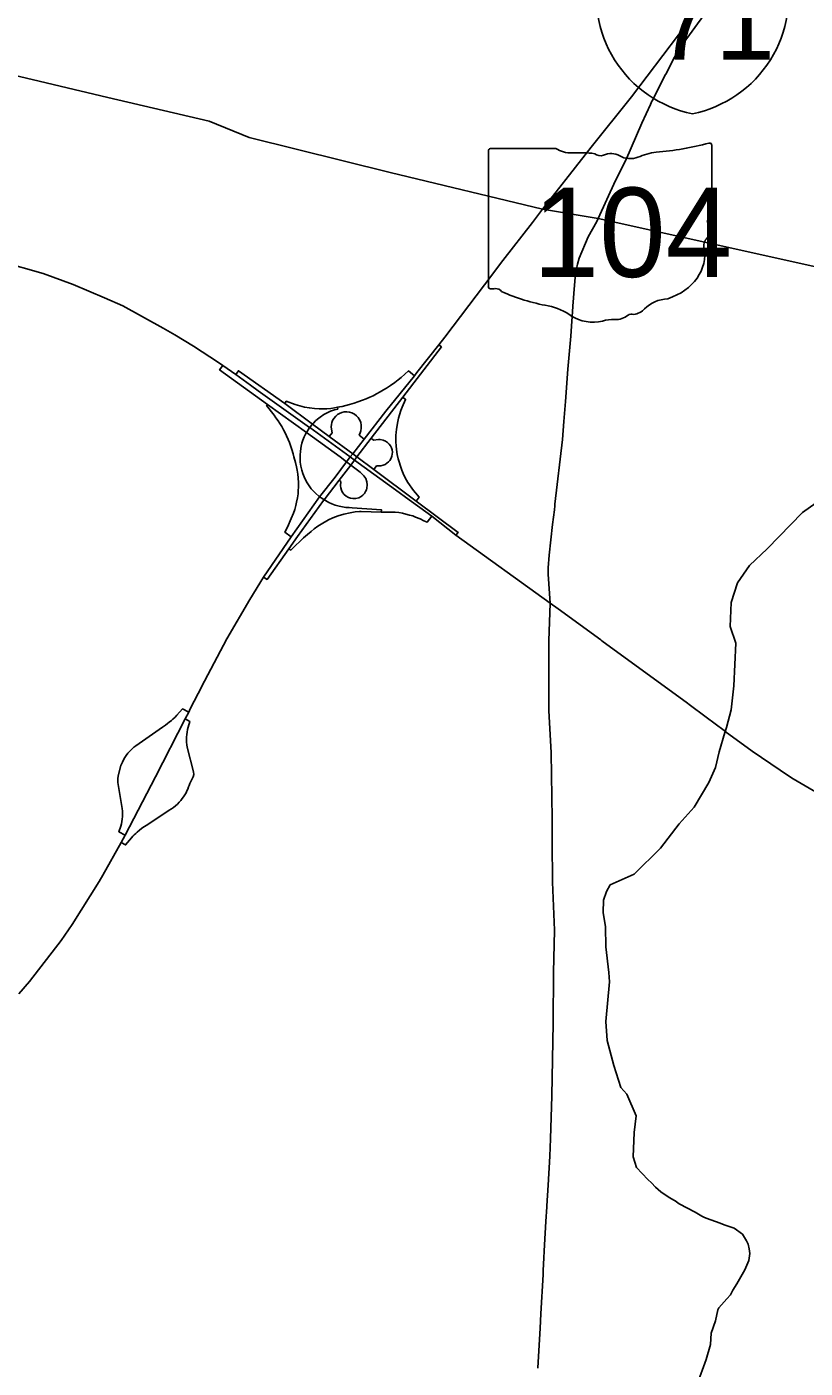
# Model space of a CAD drawing. Extents: x -1146 to -445, y -1283 to -822.
# Drawn here: x -924.4 to -894.1, y -1156.9 to -1104.6 of the extents above; entities that cross this region are included whole.
import ezdxf

# ---------------------------------------------------------------- set-up
doc = ezdxf.new("R2010")
doc.units = 0
for name, color, linetype in [('GM_X_Interchange_Ramps', 7, 'Continuous'), ('GM_X_Interstate_Route', 7, 'Continuous'), ('GM_X_Interstate_Shield', 7, 'Continuous'), ('GM_X_State_Route', 7, 'Continuous'), ('GM_X_State_Shield', 7, 'Continuous'), ('GM_X_Township', 7, 'Continuous')]:
    doc.layers.add(name, color=color, linetype=linetype)

msp = doc.modelspace()

# ---------------------------------------------------------------- linework, layer by layer
at = {"layer": 'GM_X_Interchange_Ramps'}
for points in [[(-915.223, -1126.03), (-915.087, -1126.118), (-914.237, -1124.918), (-913.9, -1124.442), (-912.889, -1123.039), (-912.867, -1123.01), (-912.283, -1122.25), (-911.827, -1121.656), (-911.679, -1121.463), (-911.587, -1121.343), (-911.029, -1120.616), (-909.799, -1119.013), (-908.294, -1117.052), (-908.395, -1116.973)], [(-916.813, -1117.78), (-916.933, -1117.944), (-915.07, -1119.293), (-913.55, -1120.395), (-912.242, -1121.342), (-911.987, -1121.535), (-911.827, -1121.656), (-911.457, -1121.935), (-911.315, -1122.072), (-911.244, -1122.188), (-911.197, -1122.31), (-911.183, -1122.431), (-911.197, -1122.556), (-911.217, -1122.622), (-911.245, -1122.687), (-911.294, -1122.763), (-911.353, -1122.828), (-911.415, -1122.877), (-911.517, -1122.93), (-911.633, -1122.96), (-911.743, -1122.963), (-911.84, -1122.947), (-911.912, -1122.922), (-912.003, -1122.87), (-912.079, -1122.804), (-912.144, -1122.721), (-912.189, -1122.63), (-912.211, -1122.551), (-912.222, -1122.468), (-912.212, -1122.305), (-912.283, -1122.25)], [(-907.727, -1124.391), (-907.645, -1124.281), (-909.28, -1123.069), (-910.923, -1121.836), (-911.587, -1121.343), (-911.749, -1121.223), (-912.661, -1120.546), (-913.313, -1120.062), (-914.399, -1119.255), (-916.199, -1117.98), (-916.308, -1118.13)], [(-909.344, -1118.176), (-909.581, -1117.991), (-909.866, -1118.241), (-909.979, -1118.334), (-910.111, -1118.436), (-910.282, -1118.558), (-910.435, -1118.66), (-910.55, -1118.731), (-910.681, -1118.808), (-910.818, -1118.883), (-910.959, -1118.955), (-911.087, -1119.016), (-911.22, -1119.074), (-911.368, -1119.135), (-911.545, -1119.2), (-911.687, -1119.248), (-911.869, -1119.302), (-912.018, -1119.342), (-912.164, -1119.372), (-912.263, -1119.392), (-912.348, -1119.403), (-912.454, -1119.426), (-912.599, -1119.449), (-912.757, -1119.461), (-912.901, -1119.466), (-913.053, -1119.464), (-913.242, -1119.453), (-913.438, -1119.43), (-913.625, -1119.396), (-913.812, -1119.352), (-913.985, -1119.301), (-914.339, -1119.174), (-914.399, -1119.255)], [(-915.07, -1119.293), (-915.106, -1119.341), (-914.81, -1119.715), (-914.739, -1119.812), (-914.651, -1119.938), (-914.589, -1120.034), (-914.514, -1120.158), (-914.443, -1120.285), (-914.371, -1120.423), (-914.326, -1120.518), (-914.261, -1120.663), (-914.213, -1120.782), (-914.171, -1120.897), (-914.121, -1121.047), (-914.071, -1121.217), (-914.04, -1121.34), (-913.978, -1121.555), (-913.936, -1121.726), (-913.911, -1121.851), (-913.887, -1122.007), (-913.871, -1122.156), (-913.861, -1122.351), (-913.862, -1122.51), (-913.869, -1122.659), (-913.88, -1122.777), (-913.903, -1122.94), (-913.933, -1123.1), (-913.964, -1123.233), (-914.008, -1123.386), (-914.056, -1123.528), (-914.141, -1123.736), (-914.285, -1124.078), (-914.392, -1124.275), (-914.14, -1124.455)], [(-909.28, -1123.069), (-909.161, -1122.909), (-909.305, -1122.744), (-909.385, -1122.646), (-909.449, -1122.56), (-909.537, -1122.433), (-909.597, -1122.336), (-909.653, -1122.241), (-909.726, -1122.103), (-909.778, -1121.993), (-909.836, -1121.859), (-909.894, -1121.7), (-909.946, -1121.536), (-909.978, -1121.414), (-910.013, -1121.249), (-910.044, -1121.053), (-910.059, -1120.905), (-910.068, -1120.748), (-910.069, -1120.611), (-910.066, -1120.5), (-910.057, -1120.372), (-910.047, -1120.27), (-910.024, -1120.107), (-909.996, -1119.959), (-909.965, -1119.829), (-909.927, -1119.695), (-909.872, -1119.531), (-909.82, -1119.399), (-909.688, -1119.1), (-909.799, -1119.013)], [(-912.348, -1119.403), (-912.335, -1119.479), (-912.453, -1119.511), (-912.614, -1119.56), (-912.748, -1119.622), (-912.874, -1119.693), (-913.015, -1119.788), (-913.121, -1119.873), (-913.194, -1119.939), (-913.279, -1120.025), (-913.313, -1120.062), (-913.351, -1120.106), (-913.423, -1120.199), (-913.44, -1120.222), (-913.521, -1120.345), (-913.55, -1120.395), (-913.584, -1120.457), (-913.636, -1120.564), (-913.688, -1120.694), (-913.725, -1120.81), (-913.755, -1120.924), (-913.788, -1121.118), (-913.801, -1121.277), (-913.802, -1121.409), (-913.793, -1121.544), (-913.772, -1121.695), (-913.737, -1121.854), (-913.695, -1121.99), (-913.646, -1122.116), (-913.592, -1122.232), (-913.527, -1122.35), (-913.451, -1122.468), (-913.364, -1122.583), (-913.279, -1122.679), (-913.187, -1122.77), (-913.064, -1122.875), (-913.041, -1122.892), (-912.958, -1122.953), (-912.867, -1123.01), (-912.814, -1123.044), (-912.679, -1123.115), (-912.558, -1123.168), (-912.43, -1123.215), (-912.279, -1123.259), (-912.141, -1123.288), (-912.02, -1123.306), (-911.888, -1123.318), (-911.774, -1123.324), (-910.634, -1123.401), (-910.635, -1123.494)], [(-912.661, -1120.546), (-912.549, -1120.396), (-912.579, -1120.254), (-912.585, -1120.169), (-912.578, -1120.08), (-912.559, -1119.997), (-912.531, -1119.924), (-912.483, -1119.839), (-912.411, -1119.752), (-912.34, -1119.693), (-912.258, -1119.644), (-912.177, -1119.611), (-912.081, -1119.589), (-911.978, -1119.583), (-911.88, -1119.595), (-911.78, -1119.625), (-911.684, -1119.674), (-911.606, -1119.733), (-911.543, -1119.799), (-911.495, -1119.867), (-911.462, -1119.934), (-911.438, -1120.002), (-911.418, -1120.106), (-911.416, -1120.217), (-911.431, -1120.32), (-911.453, -1120.397), (-911.495, -1120.491), (-911.298, -1120.644)], [(-911.029, -1120.616), (-910.934, -1120.691), (-910.751, -1120.666), (-910.677, -1120.666), (-910.566, -1120.686), (-910.473, -1120.724), (-910.395, -1120.777), (-910.331, -1120.839), (-910.28, -1120.909), (-910.244, -1120.981), (-910.218, -1121.065), (-910.206, -1121.15), (-910.209, -1121.234), (-910.226, -1121.317), (-910.255, -1121.395), (-910.303, -1121.476), (-910.351, -1121.532), (-910.418, -1121.59), (-910.485, -1121.631), (-910.561, -1121.663), (-910.652, -1121.684), (-910.819, -1121.692), (-910.923, -1121.836)], [(-914.237, -1124.918), (-914.155, -1124.972), (-913.982, -1124.797), (-913.814, -1124.635), (-913.662, -1124.495), (-913.51, -1124.36), (-913.372, -1124.243), (-913.256, -1124.148), (-913.113, -1124.041), (-912.983, -1123.956), (-912.695, -1123.798), (-912.524, -1123.721), (-912.318, -1123.642), (-912.096, -1123.574), (-911.847, -1123.517), (-911.653, -1123.487), (-911.488, -1123.47), (-911.422, -1123.466), (-910.635, -1123.494), (-910.39, -1123.489), (-910.248, -1123.489), (-910.102, -1123.495), (-909.958, -1123.512), (-909.809, -1123.538), (-909.679, -1123.566), (-909.532, -1123.605), (-909.414, -1123.642), (-909.299, -1123.683), (-909.123, -1123.755), (-908.978, -1123.826), (-908.851, -1123.887), (-908.672, -1123.646)], [(-918.138, -1131.287), (-918.375, -1131.162), (-918.599, -1131.41), (-918.668, -1131.481), (-918.751, -1131.56), (-918.812, -1131.614), (-918.894, -1131.683), (-918.958, -1131.732), (-919.042, -1131.793), (-919.161, -1131.873), (-920.196, -1132.596), (-920.269, -1132.653), (-920.343, -1132.719), (-920.422, -1132.797), (-920.502, -1132.889), (-920.567, -1132.974), (-920.62, -1133.054), (-920.675, -1133.147), (-920.721, -1133.238), (-920.785, -1133.362), (-920.88, -1133.771), (-920.893, -1133.882)], [(-917.943, -1133.715), (-917.945, -1133.615), (-918.198, -1132.651), (-918.21, -1132.556), (-918.217, -1132.457), (-918.219, -1132.366), (-918.217, -1132.266), (-918.209, -1132.165), (-918.196, -1132.066), (-918.178, -1131.971), (-918.154, -1131.87), (-918.09, -1131.654), (-918.278, -1131.555)], [(-920.893, -1133.882), (-920.897, -1134.025), (-920.737, -1134.96), (-920.725, -1135.05), (-920.717, -1135.152), (-920.714, -1135.254), (-920.718, -1135.352), (-920.728, -1135.459), (-920.742, -1135.552), (-920.759, -1135.635), (-920.786, -1135.738), (-920.855, -1135.949), (-920.613, -1136.077)], [(-920.774, -1136.366), (-920.593, -1136.462), (-920.361, -1136.184), (-920.309, -1136.126), (-920.257, -1136.072), (-920.198, -1136.014), (-920.141, -1135.962), (-920.05, -1135.886), (-919.974, -1135.827), (-919.883, -1135.764), (-919.774, -1135.695), (-918.895, -1135.114), (-918.804, -1135.057), (-918.726, -1135.001), (-918.647, -1134.938), (-918.579, -1134.876), (-918.504, -1134.8), (-918.449, -1134.737), (-918.388, -1134.66), (-918.335, -1134.586), (-918.286, -1134.507), (-918.242, -1134.43), (-918.205, -1134.354), (-918.174, -1134.284), (-918.14, -1134.201), (-918.117, -1134.141), (-918.097, -1134.073), (-917.968, -1133.807), (-917.943, -1133.715)]]:
    msp.add_lwpolyline(points, dxfattribs=at)
at = {"layer": 'GM_X_Interstate_Route'}
for points in [[(-902.461, -1109.267), (-900.891, -1107.3), (-899.054, -1104.889), (-897.704, -1103.196), (-896.327, -1101.431), (-896.05, -1101.076), (-895.664, -1100.526), (-895.305, -1099.975), (-894.933, -1099.322), (-894.547, -1098.59)], [(-904.347, -1111.675), (-902.701, -1109.567), (-902.461, -1109.267)], [(-918.68, -1116.588), (-919.128, -1116.32), (-920.698, -1115.452), (-921.421, -1115.142), (-922.643, -1114.621), (-923.8, -1114.196), (-925.452, -1113.725), (-928.801, -1112.823), (-929.653, -1112.604), (-931.972, -1112.008), (-933.318, -1111.662), (-934.577, -1111.334), (-935.141, -1111.186), (-936.719, -1110.793), (-937.723, -1110.53)], [(-906.618, -1114.634), (-905.899, -1113.688), (-904.751, -1112.204), (-904.358, -1111.689), (-904.347, -1111.675)], [(-908.163, -1116.668), (-906.618, -1114.634)], [(-916.813, -1117.78), (-916.98, -1117.663), (-917.951, -1117.023), (-918.68, -1116.588)], [(-908.395, -1116.973), (-908.165, -1116.671), (-908.163, -1116.668)], [(-909.249, -1118.056), (-908.395, -1116.973)], [(-916.308, -1118.13), (-916.813, -1117.78)], [(-911.842, -1121.343), (-913.423, -1120.199), (-913.432, -1120.192), (-915.426, -1118.767), (-915.725, -1118.55), (-916.308, -1118.13)], [(-911.842, -1121.343), (-911.749, -1121.223), (-911.298, -1120.644), (-910.456, -1119.561), (-909.344, -1118.176), (-909.249, -1118.056)], [(-914.14, -1124.455), (-913.048, -1122.902), (-913.041, -1122.892), (-912.438, -1122.133), (-911.987, -1121.535), (-911.842, -1121.343)], [(-909.943, -1122.728), (-911.679, -1121.463), (-911.842, -1121.343)], [(-903.741, -1127.268), (-904.06, -1127.035), (-907.727, -1124.391), (-908.672, -1123.646), (-909.696, -1122.909), (-909.943, -1122.728)], [(-915.223, -1126.03), (-914.14, -1124.455)], [(-917.763, -1130.558), (-917.516, -1130.079), (-916.65, -1128.428), (-915.762, -1126.895), (-915.223, -1126.03)], [(-902.043, -1128.506), (-902.086, -1128.474), (-903.741, -1127.268)], [(-898.65, -1130.986), (-898.708, -1130.943), (-902.043, -1128.506)], [(-918.076, -1131.165), (-917.763, -1130.558)], [(-919.433, -1133.812), (-919.433, -1133.812), (-918.278, -1131.555), (-918.138, -1131.287), (-918.076, -1131.165)], [(-897.282, -1132.007), (-897.976, -1131.483), (-898.65, -1130.986)], [(-894.588, -1133.882), (-894.737, -1133.793), (-896.186, -1132.807), (-897.237, -1132.041), (-897.282, -1132.007)], [(-921.487, -1137.641), (-920.774, -1136.366), (-920.613, -1136.077), (-919.433, -1133.812)], [(-889.908, -1136.261), (-890.993, -1135.789), (-892.156, -1135.231), (-892.864, -1134.871), (-893.811, -1134.345), (-894.588, -1133.882)], [(-924.752, -1142.273), (-924.336, -1141.79), (-923.11, -1140.191), (-922.672, -1139.564), (-921.629, -1137.894), (-921.487, -1137.641)]]:
    msp.add_lwpolyline(points, dxfattribs=at)
at = {"layer": 'GM_X_Interstate_Shield'}
for centre, start, end in [((-897.577, -1103.374), 165.8066, 258.463), ((-899.452, -1103.374), 281.537, 14.1934)]:
    msp.add_arc(centre, 4.688, start, end, dxfattribs=at)
at = {"layer": 'GM_X_State_Route'}
for points in [[(-899.551, -1106.418), (-899.222, -1105.756), (-898.978, -1105.371), (-897.97, -1103.984), (-896.862, -1102.61), (-896.57, -1102.284), (-896.244, -1101.94), (-895.928, -1101.644), (-895.333, -1101.143), (-895.269, -1101.093)], [(-900.094, -1107.477), (-900.089, -1107.466), (-899.563, -1106.44), (-899.551, -1106.418)], [(-902.184, -1112.047), (-902.183, -1112.045), (-901.514, -1110.571), (-901.112, -1109.775), (-900.489, -1108.339), (-900.148, -1107.599), (-900.094, -1107.477)], [(-903.171, -1115.471), (-903.11, -1114.644), (-903.066, -1114.198), (-903.035, -1114.008), (-902.993, -1113.832), (-902.926, -1113.592), (-902.579, -1112.763), (-902.242, -1112.166), (-902.184, -1112.047)], [(-903.875, -1123.181), (-903.581, -1120.661), (-903.53, -1119.964), (-903.459, -1119.178), (-903.368, -1117.92), (-903.257, -1116.628), (-903.171, -1115.474), (-903.171, -1115.471)], [(-904.109, -1129.836), (-904.108, -1128.543), (-904.108, -1128.507), (-904.06, -1127.035), (-904.141, -1125.915), (-904.139, -1125.664), (-904.095, -1125.173), (-903.964, -1123.976), (-903.895, -1123.405), (-903.883, -1123.25), (-903.879, -1123.211), (-903.875, -1123.181)], [(-903.98, -1136.267), (-903.986, -1136.138), (-903.975, -1135.44), (-904.024, -1132.87), (-904.111, -1131.224), (-904.11, -1129.921), (-904.11, -1129.893), (-904.109, -1129.836)], [(-904.05, -1147.912), (-903.991, -1146.243), (-903.94, -1143.409), (-903.929, -1141.432), (-903.886, -1139.786), (-903.967, -1137.909), (-903.977, -1136.325), (-903.98, -1136.267)], [(-904.316, -1152.805), (-904.279, -1152.055), (-904.228, -1151.141), (-904.193, -1150.564), (-904.191, -1150.527), (-904.142, -1149.721), (-904.074, -1148.593), (-904.05, -1147.912)], [(-904.535, -1156.857), (-904.534, -1156.844), (-904.448, -1155.293), (-904.418, -1154.745), (-904.335, -1153.202)], [(-904.335, -1153.202), (-904.328, -1153.051), (-904.316, -1152.805)]]:
    msp.add_lwpolyline(points, dxfattribs=at)
at = {"layer": 'GM_X_State_Shield'}
for p, q in [((-903.832, -1109.325), (-906.381, -1109.325)), ((-897.765, -1111.958), (-897.765, -1109.194)), ((-906.466, -1109.416), (-906.466, -1114.699)), ((-897.766, -1111.957), (-897.765, -1111.958))]:
    msp.add_line(p, q, dxfattribs=at)
for centre, major_axis, start_param, end_param in [((-906.366, -1109.405), (0.101, 0), 1.712693, 3.28349), ((-903.226, -1108.712), (0.978, 0), 4.042523, 4.731795), ((-900.865, -1102.123), (9.227, 0), 4.814394, 5.042369), ((-897.862, -1109.183), (0.0969, 0), 6.141152, 7.989035), ((-902.901, -1112.291), (3.51, 0), 1.404758, 1.657858), ((-902.105, -1109.378), (0.282, 0), 3.836095, 5.185415), ((-901.69, -1109.988), (0.586, 0), 0.950623, 2.079405), ((-900.934, -1109.151), (0.705, 0), 4.081561, 5.145723), ((-899.688, -1110.939), (1.856, 0), 1.699011, 2.107814), ((-897.869, -1111.969), (0.104, 0), 5.05454, 6.418171), ((-897.788, -1112.161), (0.15, 0), 1.883978, 3.671073), ((-898.741, -1112.51), (0.9, 0), 5.934695, 6.695948), ((-897.418, -1113.115), (0.655, 0), 2.387724, 3.262537), ((-900.348, -1113.466), (2.308, 0), 5.101752, 6.440018), ((-906.366, -1114.711), (0.102, 0), 3.00124, 4.508301), ((-906.35, -1114.17), (0.776, 0), 4.665946, 4.897461), ((-906.191, -1115.004), (0.28, 0), 0.519207, 1.627899), ((-902.658, -1110.257), (6.663, 0), 4.195997, 4.488961), ((-904.645, -1117.073), (2.085, 0), 0.823519, 1.323587), ((-900.976, -1115.211), (0.746, 0), 4.937069, 5.64225), ((-899.375, -1116.183), (1.264, 0), 1.647645, 2.488434), ((-902.39, -1115.03), (1.323, 0), 4.026481, 4.996735), ((-901.626, -1116.857), (1.087, 0), 1.495662, 1.94098), ((-901.529, -1115.426), (0.705, 0), 4.691044, 5.507374), ((-900.891, -1115.938), (0.198, 0), 1.147584, 2.315152)]:
    msp.add_ellipse(centre, major_axis=major_axis, ratio=0.8, start_param=start_param, end_param=end_param, dxfattribs=at)
at = {"layer": 'GM_X_Township'}
for points in [[(-891.411, -1104.525), (-891.013, -1105.536), (-890.797, -1106.62), (-890.038, -1109.149), (-889.279, -1111.425), (-888.954, -1111.93), (-888.159, -1112.508), (-887.617, -1112.653), (-885.522, -1112.833), (-885.269, -1113.05), (-884.908, -1113.917), (-884.872, -1114.387), (-885.052, -1115.145), (-885.182, -1115.826), (-902.183, -1112.045), (-904.358, -1111.689), (-910.289, -1110.249), (-915.786, -1108.893), (-917.339, -1108.257), (-921.29, -1107.327), (-927.148, -1105.948)], [(-898.329, -1157.484), (-897.985, -1156.523), (-897.812, -1155.932), (-897.785, -1155.488), (-897.621, -1155.015), (-897.526, -1154.578), (-897.485, -1154.507), (-897.177, -1154.153), (-897.035, -1154), (-896.939, -1153.814), (-896.793, -1153.569), (-896.478, -1153.021), (-896.326, -1152.659), (-896.28, -1152.391), (-896.312, -1152.207), (-896.344, -1152.024), (-896.414, -1151.89), (-896.571, -1151.639), (-896.898, -1151.406), (-897.284, -1151.27), (-897.431, -1151.202), (-897.982, -1151.005), (-898.067, -1150.975), (-898.148, -1150.93), (-898.416, -1150.783), (-899.029, -1150.448), (-899.193, -1150.339), (-899.24, -1150.308), (-899.401, -1150.219), (-899.578, -1150.096), (-899.752, -1149.989), (-899.962, -1149.798), (-900.116, -1149.627), (-900.257, -1149.5), (-900.697, -1149.032), (-900.826, -1148.615), (-900.781, -1147.677), (-900.706, -1147.019), (-901.073, -1146.184), (-901.303, -1145.913), (-901.575, -1145.055), (-901.834, -1144.086), (-901.887, -1143.349), (-901.751, -1141.803), (-901.771, -1141.437), (-901.884, -1140.433), (-901.902, -1139.655), (-901.996, -1139.103), (-901.977, -1138.622), (-901.864, -1138.285), (-901.717, -1138.019), (-900.781, -1137.6), (-899.756, -1136.586), (-899.033, -1135.647), (-898.455, -1134.997), (-897.882, -1134.036), (-897.624, -1133.443), (-897.48, -1132.829), (-897.251, -1132.085), (-897.191, -1131.89), (-897.01, -1131.203), (-896.902, -1130.264), (-896.829, -1128.602), (-897.046, -1127.952), (-897.01, -1127.013), (-896.757, -1126.254), (-896.288, -1125.568), (-895.601, -1124.918), (-894.228, -1123.509), (-893.253, -1122.822)]]:
    msp.add_lwpolyline(points, dxfattribs=at)

# ---------------------------------------------------------------- texts
at = {"layer": 'GM_X_Interstate_Shield'}
msp.add_text('71', height=3.125, dxfattribs=at).set_placement((-899.958, -1105.858))
at = {"layer": 'GM_X_State_Shield'}
msp.add_text('104', height=3.4805, dxfattribs=at).set_placement((-904.737, -1114.327))

doc.saveas('drawing.dxf')
